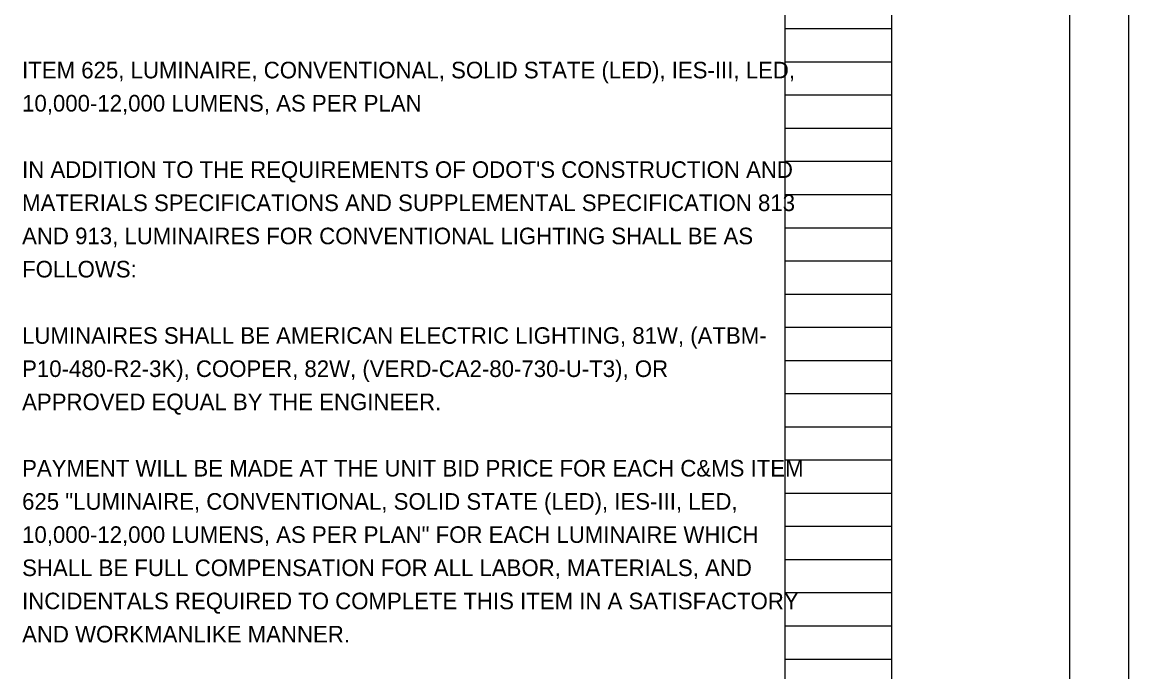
# Model space of a CAD drawing. Extents: x 0 to 49.8, y -1.8 to 22.
# Drawn here: x 24.66 to 34, y 5.35 to 10.83 of the extents above; entities that cross this region are included whole.
import ezdxf

# ---------------------------------------------------------------- set-up
doc = ezdxf.new("R2010")
doc.units = 0
for name, color, linetype in [('SH_Border', 7, 'Continuous'), ('SH_Cut_Line', 7, 'Continuous'), ('SH_Data', 7, 'Continuous'), ('SH_Text', 7, 'Continuous')]:
    doc.layers.add(name, color=color, linetype=linetype)

msp = doc.modelspace()

# ---------------------------------------------------------------- linework, layer by layer
at = {"layer": 'SH_Border'}
msp.add_line((32, 0.5), (32, 21.5), dxfattribs=at)
msp.add_lwpolyline([(1.5, 21.5), (33.5, 21.5), (33.5, 0.5), (1.5, 0.5)], close=True, dxfattribs=at)
at = {"layer": 'SH_Cut_Line'}
msp.add_lwpolyline([(0, 0), (34, 0), (34, 22), (0, 22)], close=True, dxfattribs=at)
at = {"layer": 'SH_Data'}
for p, q in [((31.1, 0.98), (31.1, 21.14)), ((32, 0.98), (32, 21.14)), ((31.1, 10.78), (32, 10.78)), ((31.1, 10.5), (32, 10.5)), ((31.1, 10.22), (32, 10.22)), ((31.1, 9.94), (32, 9.94)), ((31.1, 9.66), (32, 9.66)), ((31.1, 9.38), (32, 9.38)), ((31.1, 9.1), (32, 9.1)), ((31.1, 8.82), (32, 8.82)), ((31.1, 8.54), (32, 8.54)), ((31.1, 8.26), (32, 8.26)), ((31.1, 7.98), (32, 7.98)), ((31.1, 7.7), (32, 7.7)), ((31.1, 7.42), (32, 7.42)), ((31.1, 7.14), (32, 7.14)), ((31.1, 6.86), (32, 6.86)), ((31.1, 6.58), (32, 6.58)), ((31.1, 6.3), (32, 6.3)), ((31.1, 6.02), (32, 6.02)), ((31.1, 5.74), (32, 5.74)), ((31.1, 5.46), (32, 5.46))]:
    msp.add_line(p, q, dxfattribs=at)

# ---------------------------------------------------------------- texts
at = {"layer": 'SH_Text'}
for s, p in [('ITEM 625, LUMINAIRE, CONVENTIONAL, SOLID STATE (LED), IES-III, LED, ', (24.66, 10.36)), ('10,000-12,000 LUMENS, AS PER PLAN', (24.66, 10.08)), ("IN ADDITION TO THE REQUIREMENTS OF ODOT'S CONSTRUCTION AND ", (24.66, 9.52)), ('MATERIALS SPECIFICATIONS AND SUPPLEMENTAL SPECIFICATION 813 ', (24.66, 9.24)), ('AND 913, LUMINAIRES FOR CONVENTIONAL LIGHTING SHALL BE AS ', (24.66, 8.96)), ('FOLLOWS:', (24.66, 8.68)), ('LUMINAIRES SHALL BE AMERICAN ELECTRIC LIGHTING, 81W, (ATBM-', (24.66, 8.12)), ('P10-480-R2-3K), COOPER, 82W, (VERD-CA2-80-730-U-T3), OR ', (24.66, 7.84)), ('APPROVED EQUAL BY THE ENGINEER.', (24.66, 7.56)), ('PAYMENT WILL BE MADE AT THE UNIT BID PRICE FOR EACH C&MS ITEM ', (24.66, 7)), ('625 "LUMINAIRE, CONVENTIONAL, SOLID STATE (LED), IES-III, LED, ', (24.66, 6.72)), ('10,000-12,000 LUMENS, AS PER PLAN" FOR EACH LUMINAIRE WHICH ', (24.66, 6.44)), ('SHALL BE FULL COMPENSATION FOR ALL LABOR, MATERIALS, AND ', (24.66, 6.16)), ('INCIDENTALS REQUIRED TO COMPLETE THIS ITEM IN A SATISFACTORY ', (24.66, 5.88)), ('AND WORKMANLIKE MANNER.', (24.66, 5.6))]:
    msp.add_text(s, height=0.14, dxfattribs=at).set_placement(p)

doc.saveas('drawing.dxf')
